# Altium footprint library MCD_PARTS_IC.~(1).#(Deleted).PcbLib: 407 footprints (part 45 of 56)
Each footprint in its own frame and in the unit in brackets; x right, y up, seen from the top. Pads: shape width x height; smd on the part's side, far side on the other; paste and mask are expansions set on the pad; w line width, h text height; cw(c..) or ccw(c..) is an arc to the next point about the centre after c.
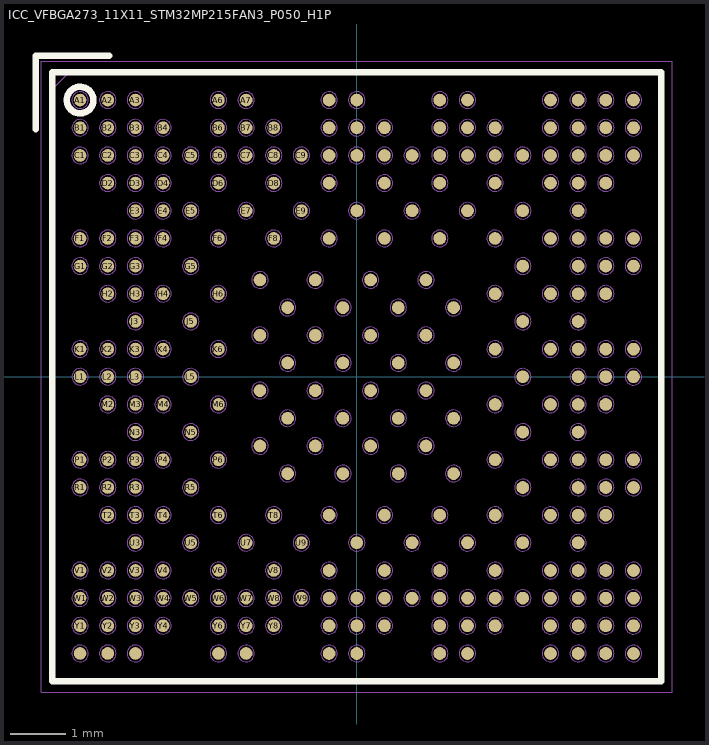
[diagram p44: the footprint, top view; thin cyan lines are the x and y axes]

## ICC_VFBGA273_11X11_STM32MP215FAN3_P050_H1P [mm]
height 1
pads (273):
  round 0.23 smd paste+0.025 mask+0.05: 1A1(-1.75,1.75) 1A3(-0.75,1.75) 1A5(0.25,1.75) 1A7(1.25,1.75) 1B2(-1.25,1.25) 1B4(-0.25,1.25) 1B6(0.75,1.25) 1B8(1.75,1.25) 1C1(-1.75,0.75) 1C3(-0.75,0.75) 1C5(0.25,0.75) 1C7(1.25,0.75) 1D2(-1.25,0.25) 1D4(-0.25,0.25) 1D6(0.75,0.25) 1D8(1.75,0.25) 1E1(-1.75,-0.25) 1E3(-0.75,-0.25) 1E5(0.25,-0.25) 1E7(1.25,-0.25) 1F2(-1.25,-0.75) 1F4(-0.25,-0.75) 1F6(0.75,-0.75) 1F8(1.75,-0.75) 1G1(-1.75,-1.25) 1G3(-0.75,-1.25) 1G5(0.25,-1.25) 1G7(1.25,-1.25) 1H2(-1.25,-1.75) 1H4(-0.25,-1.75) 1H6(0.75,-1.75) 1H8(1.75,-1.75) A1(-5,5) A2(-4.5,5) A3(-4,5) A6(-2.5,5) A7(-2,5) A10(-0.5,5) A11(0,5) A14(1.5,5) A15(2,5) A18(3.5,5) A19(4,5) A20(4.5,5) A21(5,5) AA1(-5,-5) AA2(-4.5,-5) AA3(-4,-5) AA6(-2.5,-5) AA7(-2,-5) AA10(-0.5,-5) AA11(0,-5) AA14(1.5,-5) AA15(2,-5) AA18(3.5,-5) AA19(4,-5) AA20(4.5,-5) AA21(5,-5) B1(-5,4.5) B2(-4.5,4.5) B3(-4,4.5) B4(-3.5,4.5) B6(-2.5,4.5) B7(-2,4.5) B8(-1.5,4.5) B10(-0.5,4.5) B11(0,4.5) B12(0.5,4.5) B14(1.5,4.5) B15(2,4.5) B16(2.5,4.5) B18(3.5,4.5) B19(4,4.5) B20(4.5,4.5) B21(5,4.5) C1(-5,4) C2(-4.5,4) C3(-4,4) C4(-3.5,4) C5(-3,4) C6(-2.5,4) C7(-2,4) C8(-1.5,4) C9(-1,4) C10(-0.5,4) C11(0,4) C12(0.5,4) C13(1,4) C14(1.5,4) C15(2,4) C16(2.5,4) C17(3,4) C18(3.5,4) C19(4,4) C20(4.5,4) C21(5,4) D2(-4.5,3.5) D3(-4,3.5) D4(-3.5,3.5) D6(-2.5,3.5) D8(-1.5,3.5) D10(-0.5,3.5) D12(0.5,3.5) D14(1.5,3.5) D16(2.5,3.5) D18(3.5,3.5) D19(4,3.5) D20(4.5,3.5) E3(-4,3) E4(-3.5,3) E5(-3,3) E7(-2,3) E9(-1,3) E11(0,3) E13(1,3) E15(2,3) E17(3,3) E19(4,3) F1(-5,2.5) F2(-4.5,2.5) F3(-4,2.5) F4(-3.5,2.5) F6(-2.5,2.5) F8(-1.5,2.5) F10(-0.5,2.5) F12(0.5,2.5) F14(1.5,2.5) F16(2.5,2.5) F18(3.5,2.5) F19(4,2.5) F20(4.5,2.5) F21(5,2.5) G1(-5,2) G2(-4.5,2) G3(-4,2) G5(-3,2) G17(3,2) G19(4,2) G20(4.5,2) G21(5,2) H2(-4.5,1.5) H3(-4,1.5) H4(-3.5,1.5) H6(-2.5,1.5) H16(2.5,1.5) H18(3.5,1.5) H19(4,1.5) H20(4.5,1.5) J3(-4,1) J5(-3,1) J17(3,1) J19(4,1) K1(-5,0.5) K2(-4.5,0.5) K3(-4,0.5) K4(-3.5,0.5) K6(-2.5,0.5) K16(2.5,0.5) K18(3.5,0.5) K19(4,0.5) K20(4.5,0.5) K21(5,0.5) L1(-5,0) L2(-4.5,0) L3(-4,0) L5(-3,0) L17(3,0) L19(4,0) L20(4.5,0) L21(5,0) M2(-4.5,-0.5) M3(-4,-0.5) M4(-3.5,-0.5) M6(-2.5,-0.5) M16(2.5,-0.5) M18(3.5,-0.5) M19(4,-0.5) M20(4.5,-0.5) N3(-4,-1) N5(-3,-1) N17(3,-1) N19(4,-1) P1(-5,-1.5) P2(-4.5,-1.5) P3(-4,-1.5) P4(-3.5,-1.5) P6(-2.5,-1.5) P16(2.5,-1.5) P18(3.5,-1.5) P19(4,-1.5) P20(4.5,-1.5) P21(5,-1.5) R1(-5,-2) R2(-4.5,-2) R3(-4,-2) R5(-3,-2) R17(3,-2) R19(4,-2) R20(4.5,-2) R21(5,-2) T2(-4.5,-2.5) T3(-4,-2.5) T4(-3.5,-2.5) T6(-2.5,-2.5) T8(-1.5,-2.5) T10(-0.5,-2.5) T12(0.5,-2.5) T14(1.5,-2.5) T16(2.5,-2.5) T18(3.5,-2.5) T19(4,-2.5) T20(4.5,-2.5) U3(-4,-3) U5(-3,-3) U7(-2,-3) U9(-1,-3) U11(0,-3) U13(1,-3) U15(2,-3) U17(3,-3) U19(4,-3) V1(-5,-3.5) V2(-4.5,-3.5) V3(-4,-3.5) V4(-3.5,-3.5) V6(-2.5,-3.5) V8(-1.5,-3.5) V10(-0.5,-3.5) V12(0.5,-3.5) V14(1.5,-3.5) V16(2.5,-3.5) V18(3.5,-3.5) V19(4,-3.5) V20(4.5,-3.5) V21(5,-3.5) W1(-5,-4) W2(-4.5,-4) W3(-4,-4) W4(-3.5,-4) W5(-3,-4) W6(-2.5,-4) W7(-2,-4) W8(-1.5,-4) W9(-1,-4) W10(-0.5,-4) W11(0,-4) W12(0.5,-4) W13(1,-4) W14(1.5,-4) W15(2,-4) W16(2.5,-4) W17(3,-4) W18(3.5,-4) W19(4,-4) W20(4.5,-4) W21(5,-4) Y1(-5,-4.5) Y2(-4.5,-4.5) Y3(-4,-4.5) Y4(-3.5,-4.5) Y6(-2.5,-4.5) Y7(-2,-4.5) Y8(-1.5,-4.5) Y10(-0.5,-4.5) Y11(0,-4.5) Y12(0.5,-4.5) Y14(1.5,-4.5) Y15(2,-4.5) Y16(2.5,-4.5) Y18(3.5,-4.5) Y19(4,-4.5) Y20(4.5,-4.5) Y21(5,-4.5)
Top Layer:
  lines w0.1: 4.5,2.5 ccw(c4.5,2.5) 4.5,2.5
Top Overlay:
  circle w0.12: c-5,5 r0.24
  lines w0.12: -5.8,4.475 -5.8,5.8 -4.475,5.8 ; -5.5,-5.5 -5.5,5.5 5.5,5.5 5.5,-5.5 -5.5,-5.5
M14-Top Assembly:
  drawing of 279 lines, arcs and shapes, not listed
  text "A1" at -5.25,4.8 h0.4
  text "'.Designator'" at 0,0 h0.75
M16-Top Courtyard:
  lines w0.01: -5.7,-5.7 5.7,-5.7 5.7,5.7 -5.7,5.7 -5.7,-5.7
3D body: height 0.36, standoff -0.04, extent 1.55,-1.95 1.95,-1.55
3D body: height 0.36, standoff -0.04, extent 0.55,-1.95 0.95,-1.55
3D body: height 0.36, standoff -0.04, extent -0.45,-1.95 -0.05,-1.55
3D body: height 0.36, standoff -0.04, extent -1.45,-1.95 -1.05,-1.55
3D body: height 0.36, standoff -0.04, extent 1.05,-1.45 1.45,-1.05
3D body: height 0.36, standoff -0.04, extent 0.05,-1.45 0.45,-1.05
3D body: height 0.36, standoff -0.04, extent -0.95,-1.45 -0.55,-1.05
3D body: height 0.36, standoff -0.04, extent -1.95,-1.45 -1.55,-1.05
3D body: height 0.36, standoff -0.04, extent 1.55,-0.95 1.95,-0.55
3D body: height 0.36, standoff -0.04, extent 0.55,-0.95 0.95,-0.55
3D body: height 0.36, standoff -0.04, extent -0.45,-0.95 -0.05,-0.55
3D body: height 0.36, standoff -0.04, extent -1.45,-0.95 -1.05,-0.55
3D body: height 0.36, standoff -0.04, extent 1.05,-0.45 1.45,-0.05
3D body: height 0.36, standoff -0.04, extent 0.05,-0.45 0.45,-0.05
3D body: height 0.36, standoff -0.04, extent -0.95,-0.45 -0.55,-0.05
3D body: height 0.36, standoff -0.04, extent -1.95,-0.45 -1.55,-0.05
3D body: height 0.36, standoff -0.04, extent 1.55,0.05 1.95,0.45
3D body: height 0.36, standoff -0.04, extent 0.55,0.05 0.95,0.45
3D body: height 0.36, standoff -0.04, extent -0.45,0.05 -0.05,0.45
3D body: height 0.36, standoff -0.04, extent -1.45,0.05 -1.05,0.45
3D body: height 0.36, standoff -0.04, extent 1.05,0.55 1.45,0.95
3D body: height 0.36, standoff -0.04, extent 0.05,0.55 0.45,0.95
3D body: height 0.36, standoff -0.04, extent -0.95,0.55 -0.55,0.95
3D body: height 0.36, standoff -0.04, extent -1.95,0.55 -1.55,0.95
3D body: height 0.36, standoff -0.04, extent -1.45,1.05 -1.05,1.45
3D body: height 0.36, standoff -0.04, extent -0.45,1.05 -0.05,1.45
3D body: height 0.36, standoff -0.04, extent 0.55,1.05 0.95,1.45
3D body: height 0.36, standoff -0.04, extent 1.55,1.05 1.95,1.45
3D body: height 0.36, standoff -0.04, extent 1.05,1.55 1.45,1.95
3D body: height 0.36, standoff -0.04, extent 0.05,1.55 0.45,1.95
3D body: height 0.36, standoff -0.04, extent -0.95,1.55 -0.55,1.95
3D body: height 0.36, standoff -0.04, extent -1.95,1.55 -1.55,1.95
3D body: height 0.36, standoff -0.04, extent -0.7,2.3 -0.3,2.7
3D body: height 0.36, standoff -0.04, extent -0.7,-2.7 -0.3,-2.3
3D body: height 1.01, standoff 1, extent -5.3,4.7 -4.7,5.3
3D body: height 0.36, standoff -0.04, extent 4.3,-5.2 4.7,-4.8
3D body: height 0.36, standoff -0.04, extent 4.8,-4.7 5.2,-4.3
3D body: height 0.36, standoff -0.04, extent 3.8,-5.2 4.2,-4.8
3D body: height 0.36, standoff -0.04, extent 1.3,-4.7 1.7,-4.3
3D body: height 0.36, standoff -0.04, extent 2.3,-4.7 2.7,-4.3
3D body: height 0.36, standoff -0.04, extent -4.2,-5.2 -3.8,-4.8
3D body: height 0.36, standoff -0.04, extent -4.2,-4.7 -3.8,-4.3
3D body: height 0.36, standoff -0.04, extent -2.2,-4.7 -1.8,-4.3
3D body: height 0.36, standoff -0.04, extent -1.7,-4.7 -1.3,-4.3
3D body: height 0.36, standoff -0.04, extent -0.7,-5.2 -0.3,-4.8
3D body: height 0.36, standoff -0.04, extent 4.3,-4.7 4.7,-4.3
3D body: height 0.36, standoff -0.04, extent 3.8,-4.7 4.2,-4.3
3D body: height 0.36, standoff -0.04, extent 3.3,-5.2 3.699,-4.8
3D body: height 0.36, standoff -0.04, extent -0.2,-4.7 0.2,-4.3
3D body: height 0.36, standoff -0.04, extent 1.8,-5.2 2.2,-4.8
3D body: height 0.36, standoff -0.04, extent -5.2,-5.2 -4.8,-4.8
3D body: height 0.36, standoff -0.04, extent -4.7,-5.2 -4.3,-4.8
3D body: height 0.36, standoff -0.04, extent -2.7,-5.2 -2.3,-4.8
3D body: height 0.36, standoff -0.04, extent -2.2,-5.2 -1.8,-4.8
3D body: height 0.36, standoff -0.04, extent 4.8,-5.2 5.2,-4.8
3D body: height 0.36, standoff -0.04, extent 3.3,-4.7 3.7,-4.3
3D body: height 0.36, standoff -0.04, extent -0.7,-4.7 -0.3,-4.3
3D body: height 0.36, standoff -0.04, extent 0.3,-4.7 0.7,-4.3
3D body: height 0.36, standoff -0.04, extent 1.8,-4.7 2.2,-4.3
3D body: height 0.36, standoff -0.04, extent -5.2,-4.7 -4.8,-4.3
3D body: height 0.36, standoff -0.04, extent -4.7,-4.7 -4.3,-4.3
3D body: height 0.36, standoff -0.04, extent -3.7,-4.7 -3.3,-4.3
3D body: height 0.36, standoff -0.04, extent -2.7,-4.7 -2.3,-4.3
3D body: height 0.36, standoff -0.04, extent 4.8,-3.7 5.2,-3.3
3D body: height 0.36, standoff -0.04, extent 4.3,-3.7 4.7,-3.3
3D body: height 0.36, standoff -0.04, extent 3.8,-3.7 4.2,-3.3
3D body: height 0.36, standoff -0.04, extent 4.8,-4.2 5.2,-3.8
3D body: height 0.36, standoff -0.04, extent 4.3,-4.2 4.7,-3.8
3D body: height 0.36, standoff -0.04, extent 0.8,-4.2 1.2,-3.8
3D body: height 0.36, standoff -0.04, extent 2.3,-3.7 2.7,-3.3
3D body: height 0.36, standoff -0.04, extent -4.7,-3.7 -4.3,-3.3
3D body: height 0.36, standoff -0.04, extent -4.2,-3.7 -3.8,-3.3
3D body: height 0.36, standoff -0.04, extent -3.2,-4.2 -2.8,-3.8
3D body: height 0.36, standoff -0.04, extent -1.7,-3.7 -1.3,-3.3
3D body: height 0.36, standoff -0.04, extent 4.3,-2.7 4.7,-2.3
3D body: height 0.36, standoff -0.04, extent 3.8,-2.7 4.2,-2.3
3D body: height 0.36, standoff -0.04, extent 3.8,-3.2 4.2,-2.8
3D body: height 0.36, standoff -0.04, extent 2.8,-3.2 3.2,-2.8
3D body: height 0.36, standoff -0.04, extent -1.2,-3.2 -0.8,-2.8
3D body: height 0.36, standoff -0.04, extent 0.8,-3.2 1.2,-2.8
3D body: height 0.36, standoff -0.04, extent 1.8,-3.2 2.2,-2.8
3D body: height 0.36, standoff -0.04, extent -4.2,-3.2 -3.8,-2.8
3D body: height 0.36, standoff -0.04, extent -3.2,-3.2 -2.8,-2.8
3D body: height 0.36, standoff -0.04, extent -2.2,-3.2 -1.8,-2.8
3D body: height 0.36, standoff -0.04, extent 4.8,-2.2 5.2,-1.8
3D body: height 0.36, standoff -0.04, extent 4.3,-2.2 4.7,-1.8
3D body: height 0.36, standoff -0.04, extent 3.8,-2.2 4.2,-1.8
3D body: height 0.36, standoff -0.04, extent 2.8,-2.2 3.2,-1.8
3D body: height 0.36, standoff -0.04, extent -4.7,-2.2 -4.3,-1.8
3D body: height 0.36, standoff -0.04, extent -4.2,-2.2 -3.8,-1.8
3D body: height 0.36, standoff -0.04, extent -3.2,-2.2 -2.8,-1.8
3D body: height 0.36, standoff -0.04, extent 3.8,-1.2 4.2,-0.8
3D body: height 0.36, standoff -0.04, extent 4.3,-1.7 4.7,-1.3
3D body: height 0.36, standoff -0.04, extent 3.8,-1.7 4.2,-1.3
3D body: height 0.36, standoff -0.04, extent 2.8,-1.2 3.2,-0.8
3D body: height 0.36, standoff -0.04, extent -4.2,-1.2 -3.8,-0.8
3D body: height 0.36, standoff -0.04, extent -3.2,-1.2 -2.8,-0.8
3D body: height 0.36, standoff -0.04, extent 4.3,-0.7 4.7,-0.3
3D body: height 0.36, standoff -0.04, extent 3.8,-0.7 4.2,-0.3
3D body: height 0.36, standoff -0.04, extent -4.7,-0.7 -4.3,-0.3
3D body: height 0.36, standoff -0.04, extent -4.2,-0.7 -3.8,-0.3
3D body: height 0.36, standoff -0.04, extent 4.3,-0.2 4.7,0.2
3D body: height 0.36, standoff -0.04, extent 3.8,-0.2 4.2,0.2
3D body: height 0.36, standoff -0.04, extent 4.3,0.3 4.7,0.7
3D body: height 0.36, standoff -0.04, extent 3.8,0.3 4.2,0.7
3D body: height 0.36, standoff -0.04, extent -5.2,0.3 -4.8,0.7
3D body: height 0.36, standoff -0.04, extent -4.7,0.3 -4.3,0.7
3D body: height 0.36, standoff -0.04, extent -4.2,0.3 -3.8,0.7
3D body: height 0.36, standoff -0.04, extent 4.8,0.3 5.2,0.7
3D body: height 0.36, standoff -0.04, extent 3.8,0.8 4.2,1.2
3D body: height 0.36, standoff -0.04, extent 2.8,0.8 3.2,1.2
3D body: height 0.36, standoff -0.04, extent -4.2,0.8 -3.8,1.2
3D body: height 0.36, standoff -0.04, extent -3.2,0.8 -2.8,1.2
3D body: height 0.36, standoff -0.04, extent 4.3,1.3 4.7,1.7
3D body: height 0.36, standoff -0.04, extent 4.8,1.8 5.2,2.2
3D body: height 0.36, standoff -0.04, extent 4.3,1.8 4.7,2.2
3D body: height 0.36, standoff -0.04, extent 3.8,1.8 4.2,2.2
3D body: height 0.36, standoff -0.04, extent 2.8,1.8 3.2,2.2
3D body: height 0.36, standoff -0.04, extent -5.2,1.8 -4.8,2.2
3D body: height 0.36, standoff -0.04, extent -4.7,1.8 -4.3,2.2
3D body: height 0.36, standoff -0.04, extent -4.2,1.8 -3.8,2.2
3D body: height 0.36, standoff -0.04, extent -3.2,1.8 -2.8,2.2
3D body: height 0.36, standoff -0.04, extent 4.8,2.3 5.2,2.7
3D body: height 0.36, standoff -0.04, extent 2.8,2.8 3.2,3.2
3D body: height 0.36, standoff -0.04, extent 1.8,2.8 2.2,3.2
3D body: height 0.36, standoff -0.04, extent -2.2,2.8 -1.8,3.2
3D body: height 0.36, standoff -0.04, extent -0.2,2.8 0.2,3.2
3D body: height 0.36, standoff -0.04, extent 0.8,2.8 1.2,3.2
3D body: height 0.36, standoff -0.04, extent -5.2,2.3 -4.8,2.7
3D body: height 0.36, standoff -0.04, extent -4.7,2.3 -4.3,2.7
3D body: height 0.36, standoff -0.04, extent -4.2,2.3 -3.8,2.7
3D body: height 0.36, standoff -0.04, extent -3.2,2.8 -2.8,3.2
3D body: height 0.36, standoff -0.04, extent 3.8,2.8 4.2,3.2
3D body: height 0.36, standoff -0.04, extent 4.3,3.3 4.7,3.7
3D body: height 0.36, standoff -0.04, extent 3.8,3.3 4.2,3.7
3D body: height 0.36, standoff -0.04, extent -1.2,2.8 -0.8,3.2
3D body: height 0.36, standoff -0.04, extent 1.3,3.3 1.7,3.7
3D body: height 0.36, standoff -0.04, extent 2.3,3.3 2.7,3.7
3D body: height 0.36, standoff -0.04, extent -4.7,3.3 -4.3,3.7
3D body: height 0.36, standoff -0.04, extent -4.2,3.3 -3.8,3.7
3D body: height 0.36, standoff -0.04, extent -2.7,3.3 -2.3,3.7
3D body: height 0.36, standoff -0.04, extent -1.7,3.3 -1.3,3.7
3D body: height 0.36, standoff -0.04, extent 4.8,4.3 5.2,4.7
3D body: height 0.36, standoff -0.04, extent 4.3,4.3 4.7,4.7
3D body: height 0.36, standoff -0.04, extent 3.8,4.3 4.2,4.7
3D body: height 0.36, standoff -0.04, extent 3.3,4.3 3.7,4.7
3D body: height 0.36, standoff -0.04, extent -2.7,4.3 -2.3,4.7
3D body: height 0.36, standoff -0.04, extent -0.7,4.8 -0.3,5.2
3D body: height 0.36, standoff -0.04, extent 1.3,4.3 1.7,4.7
3D body: height 0.36, standoff -0.04, extent 1.8,4.3 2.2,4.7
3D body: height 0.36, standoff -0.04, extent 2.3,4.3 2.7,4.7
3D body: height 0.36, standoff -0.04, extent -5.2,4.3 -4.8,4.7
3D body: height 0.36, standoff -0.04, extent -4.7,4.3 -4.3,4.7
3D body: height 0.36, standoff -0.04, extent -4.2,4.3 -3.8,4.7
3D body: height 0.36, standoff -0.04, extent -3.7,4.3 -3.3,4.7
3D body: height 0.36, standoff -0.04, extent -2.7,4.8 -2.3,5.2
3D body: height 0.36, standoff -0.04, extent -4.2,4.8 -3.8,5.2
3D body: height 0.36, standoff -0.04, extent -4.7,4.8 -4.3,5.2
3D body: height 0.36, standoff -0.04, extent -5.2,4.8 -4.8,5.2
3D body: height 0.36, standoff -0.04, extent 1.8,4.8 2.2,5.2
3D body: height 0.36, standoff -0.04, extent -2.2,4.8 -1.8,5.2
3D body: height 0.36, standoff -0.04, extent 3.3,4.8 3.7,5.2
3D body: height 0.36, standoff -0.04, extent 3.8,4.8 4.2,5.2
3D body: height 0.36, standoff -0.04, extent 4.3,4.8 4.7,5.2
3D body: height 1, standoff 0.3, extent -5.5,-5.524 5.5,5.524
3D body: height 0.36, standoff -0.04, extent 4.8,4.8 5.2,5.2
3D body: height 0.36, standoff -0.04, extent 0.3,4.3 0.7,4.7
3D body: height 0.36, standoff -0.04, extent -0.2,4.3 0.2,4.7
3D body: height 0.36, standoff -0.04, extent -0.7,4.3 -0.3,4.7
3D body: height 0.36, standoff -0.04, extent -1.7,4.3 -1.3,4.7
3D body: height 0.36, standoff -0.04, extent -2.2,4.3 -1.8,4.7
3D body: height 0.36, standoff -0.04, extent -5.2,3.8 -4.8,4.2
3D body: height 0.36, standoff -0.04, extent -4.7,3.8 -4.3,4.2
3D body: height 0.36, standoff -0.04, extent -4.2,3.8 -3.8,4.2
3D body: height 0.36, standoff -0.04, extent -3.7,3.8 -3.3,4.2
3D body: height 0.36, standoff -0.04, extent -3.2,3.8 -2.8,4.2
3D body: height 0.36, standoff -0.04, extent -2.7,3.8 -2.3,4.2
3D body: height 0.36, standoff -0.04, extent -2.2,3.8 -1.8,4.2
3D body: height 0.36, standoff -0.04, extent -1.7,3.8 -1.3,4.2
3D body: height 0.36, standoff -0.04, extent -1.2,3.8 -0.8,4.2
3D body: height 0.36, standoff -0.04, extent -0.7,3.8 -0.3,4.2
3D body: height 0.36, standoff -0.04, extent -0.2,3.8 0.2,4.2
3D body: height 0.36, standoff -0.04, extent 0.3,3.8 0.7,4.2
3D body: height 0.36, standoff -0.04, extent 0.8,3.8 1.2,4.2
3D body: height 0.36, standoff -0.04, extent 1.3,3.8 1.7,4.2
3D body: height 0.36, standoff -0.04, extent 1.8,3.8 2.2,4.2
3D body: height 0.36, standoff -0.04, extent 2.3,3.8 2.7,4.2
3D body: height 0.36, standoff -0.04, extent 2.8,3.8 3.2,4.2
3D body: height 0.36, standoff -0.04, extent 3.3,3.8 3.7,4.2
3D body: height 0.36, standoff -0.04, extent 3.8,3.8 4.2,4.2
3D body: height 0.36, standoff -0.04, extent 4.3,3.8 4.7,4.2
3D body: height 0.36, standoff -0.04, extent 4.8,3.8 5.2,4.2
3D body: height 0.36, standoff -0.04, extent -4.2,2.8 -3.8,3.2
3D body: height 0.36, standoff -0.04, extent 4.3,2.3 4.7,2.7
3D body: height 0.36, standoff -0.04, extent 3.8,2.3 4.2,2.7
3D body: height 0.36, standoff -0.04, extent 3.3,2.3 3.7,2.7
3D body: height 0.36, standoff -0.04, extent -3.7,2.3 -3.3,2.7
3D body: height 0.36, standoff -0.04, extent 3.8,1.3 4.2,1.7
3D body: height 0.36, standoff -0.04, extent 3.3,1.3 3.7,1.7
3D body: height 0.36, standoff -0.04, extent -3.7,1.3 -3.3,1.7
3D body: height 0.36, standoff -0.04, extent -4.2,1.3 -3.8,1.7
3D body: height 0.36, standoff -0.04, extent -4.7,1.3 -4.3,1.7
3D body: height 0.36, standoff -0.04, extent 2.8,-0.2 3.2,0.2
3D body: height 0.36, standoff -0.04, extent -4.7,-0.2 -4.3,0.2
3D body: height 0.36, standoff -0.04, extent -4.2,-0.2 -3.8,0.2
3D body: height 0.36, standoff -0.04, extent -3.2,-0.2 -2.8,0.2
3D body: height 0.36, standoff -0.04, extent -4.7,-1.7 -4.3,-1.3
3D body: height 0.36, standoff -0.04, extent -4.2,-1.7 -3.8,-1.3
3D body: height 0.36, standoff -0.04, extent -3.7,-1.7 -3.3,-1.3
3D body: height 0.36, standoff -0.04, extent 3.3,-1.7 3.7,-1.3
3D body: height 0.36, standoff -0.04, extent 3.3,-2.7 3.7,-2.3
3D body: height 0.36, standoff -0.04, extent -0.2,-3.2 0.2,-2.8
3D body: height 0.36, standoff -0.04, extent -5.2,-2.2 -4.8,-1.8
3D body: height 0.36, standoff -0.04, extent -4.7,-2.7 -4.3,-2.3
3D body: height 0.36, standoff -0.04, extent -4.2,-2.7 -3.8,-2.3
3D body: height 0.36, standoff -0.04, extent -3.7,-2.7 -3.3,-2.3
3D body: height 0.36, standoff -0.04, extent 3.8,-4.2 4.2,-3.8
3D body: height 0.36, standoff -0.04, extent 3.3,-4.2 3.7,-3.8
3D body: height 0.36, standoff -0.04, extent 2.8,-4.2 3.2,-3.8
3D body: height 0.36, standoff -0.04, extent 2.3,-4.2 2.7,-3.8
3D body: height 0.36, standoff -0.04, extent 1.8,-4.2 2.2,-3.8
3D body: height 0.36, standoff -0.04, extent 1.3,-3.7 1.7,-3.3
3D body: height 0.36, standoff -0.04, extent 1.3,-4.2 1.7,-3.8
3D body: height 0.36, standoff -0.04, extent 0.3,-4.2 0.7,-3.8
3D body: height 0.36, standoff -0.04, extent -0.2,-4.2 0.2,-3.8
3D body: height 0.36, standoff -0.04, extent -0.7,-4.2 -0.3,-3.8
3D body: height 0.36, standoff -0.04, extent -1.2,-4.2 -0.8,-3.8
3D body: height 0.36, standoff -0.04, extent -1.7,-4.2 -1.3,-3.8
3D body: height 0.36, standoff -0.04, extent -2.2,-4.2 -1.8,-3.8
3D body: height 0.36, standoff -0.04, extent -2.7,-3.7 -2.3,-3.3
3D body: height 0.36, standoff -0.04, extent -2.7,-4.2 -2.3,-3.8
3D body: height 0.36, standoff -0.04, extent -3.7,-4.2 -3.3,-3.8
3D body: height 0.36, standoff -0.04, extent -5.2,-3.7 -4.8,-3.3
3D body: height 0.36, standoff -0.04, extent -5.2,-4.2 -4.8,-3.8
3D body: height 0.36, standoff -0.04, extent -4.7,-4.2 -4.3,-3.8
3D body: height 0.36, standoff -0.04, extent -4.2,-4.2 -3.8,-3.8
3D body: height 0.36, standoff -0.04, extent -0.2,4.8 0.2,5.2
3D body: height 0.36, standoff -0.04, extent 1.3,4.8 1.7,5.2
3D body: height 0.36, standoff -0.04, extent -3.7,3.3 -3.3,3.7
3D body: height 0.36, standoff -0.04, extent -0.7,3.3 -0.3,3.7
3D body: height 0.36, standoff -0.04, extent 0.3,3.3 0.7,3.7
3D body: height 0.36, standoff -0.04, extent 3.3,3.3 3.7,3.7
3D body: height 0.36, standoff -0.04, extent -3.7,2.8 -3.3,3.2
3D body: height 0.36, standoff -0.04, extent -2.7,2.3 -2.3,2.7
3D body: height 0.36, standoff -0.04, extent -1.7,2.3 -1.3,2.7
3D body: height 0.36, standoff -0.04, extent 0.3,2.3 0.7,2.7
3D body: height 0.36, standoff -0.04, extent 1.3,2.3 1.7,2.7
3D body: height 0.36, standoff -0.04, extent 2.3,2.3 2.7,2.7
3D body: height 0.36, standoff -0.04, extent -2.7,1.3 -2.3,1.7
3D body: height 0.36, standoff -0.04, extent 2.3,1.3 2.7,1.7
3D body: height 0.36, standoff -0.04, extent -3.7,0.3 -3.3,0.7
3D body: height 0.36, standoff -0.04, extent -2.7,0.3 -2.3,0.7
3D body: height 0.36, standoff -0.04, extent 3.3,0.3 3.7,0.7
3D body: height 0.36, standoff -0.04, extent 2.3,0.3 2.7,0.7
3D body: height 0.36, standoff -0.04, extent -5.2,-0.2 -4.8,0.2
3D body: height 0.36, standoff -0.04, extent 4.8,-0.2 5.2,0.2
3D body: height 0.36, standoff -0.04, extent -3.7,-0.7 -3.3,-0.3
3D body: height 0.36, standoff -0.04, extent -2.7,-0.7 -2.3,-0.3
3D body: height 0.36, standoff -0.04, extent 3.3,-0.7 3.7,-0.3
3D body: height 0.36, standoff -0.04, extent 2.3,-0.7 2.7,-0.3
3D body: height 0.36, standoff -0.04, extent -5.2,-1.7 -4.8,-1.3
3D body: height 0.36, standoff -0.04, extent -2.7,-1.7 -2.3,-1.3
3D body: height 0.36, standoff -0.04, extent 4.8,-1.7 5.2,-1.3
3D body: height 0.36, standoff -0.04, extent 2.3,-1.7 2.7,-1.3
3D body: height 0.36, standoff -0.04, extent -2.7,-2.7 -2.3,-2.3
3D body: height 0.36, standoff -0.04, extent -1.7,-2.7 -1.3,-2.3
3D body: height 0.36, standoff -0.04, extent -0.7,-2.7 -0.3,-2.3
3D body: height 0.36, standoff -0.04, extent 0.3,-2.7 0.7,-2.3
3D body: height 0.36, standoff -0.04, extent 1.3,-2.7 1.7,-2.3
3D body: height 0.36, standoff -0.04, extent 2.3,-2.7 2.7,-2.3
3D body: height 0.36, standoff -0.04, extent -3.7,-3.7 -3.3,-3.3
3D body: height 0.36, standoff -0.04, extent -0.7,-3.7 -0.3,-3.3
3D body: height 0.36, standoff -0.04, extent 0.3,-3.7 0.7,-3.3
3D body: height 0.36, standoff -0.04, extent 3.3,-3.7 3.7,-3.3
3D body: height 0.36, standoff -0.04, extent -0.2,-5.2 0.2,-4.8
3D body: height 0.36, standoff -0.04, extent 1.3,-5.2 1.7,-4.8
